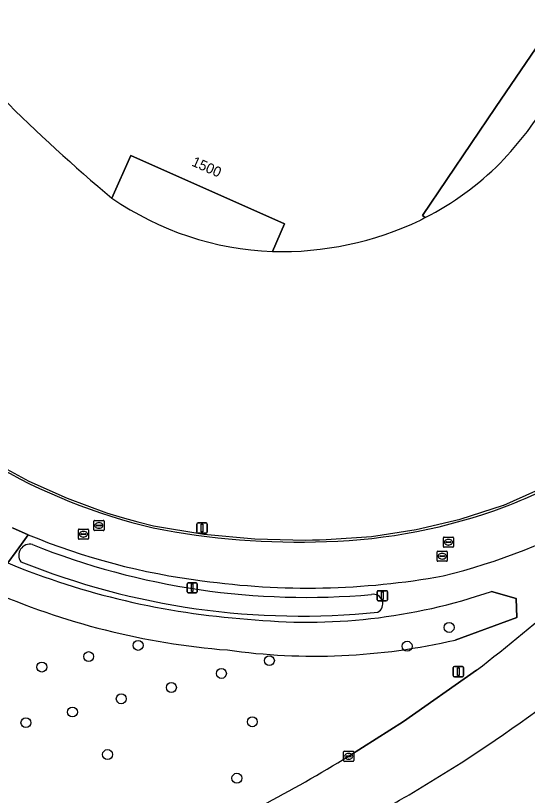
# Model space of a CAD drawing. Extents: x 155018 to 156648, y 383979 to 385733.
# Drawn here: x 155811.6 to 155861.9, y 384237.5 to 384314.2 of the extents above; entities that cross this region are included whole.
import ezdxf

# ---------------------------------------------------------------- set-up
doc = ezdxf.new("R2010")
doc.units = 0
for name, color, linetype in [('IMGEO_Berm_groen', 7, 'Continuous'), ('IMGEO_Boom', 7, 'Continuous'), ('IMGEO_Erf', 7, 'Continuous'), ('IMGEO_Groenvoorziening', 7, 'Continuous'), ('IMGEO_Kolk', 7, 'Continuous'), ('IMGEO_Lichtmast', 7, 'Continuous'), ('IMGEO_Lijnafwatering', 7, 'Continuous'), ('IMGEO_Loofbos', 7, 'Continuous'), ('IMGEO_Pand', 7, 'Continuous'), ('IMGEO_Pand_nummerreeks', 7, 'Continuous'), ('IMGEO_Pand_overbouw', 7, 'Continuous'), ('IMGEO_Rijbaan_lokaal_gesloten', 7, 'Continuous'), ('IMGEO_Rijbaan_regionaal_gesloten', 7, 'Continuous'), ('IMGEO_Rioolput', 7, 'Continuous'), ('IMGEO_Verkeersbordpaal', 7, 'Continuous'), ('IMGEO_Voetpad_halfverhard', 7, 'Continuous'), ('IMGEO_Waterloop', 7, 'Continuous')]:
    doc.layers.add(name, color=color, linetype=linetype)

msp = doc.modelspace()

# ---------------------------------------------------------------- linework, layer by layer
at = {"layer": 'IMGEO_Berm_groen'}
for centre, radius, start, end in [((155773.683, 384367.762), 151.05, 300.47999, 312.64177), ((155821.116, 384295.176), 73.267, 303.48216, 324.29176), ((155768.291, 384380.188), 164.502, 298.36779, 299.90303)]:
    msp.add_arc(centre, radius, start, end, dxfattribs=at)
at = {"layer": 'IMGEO_Boom'}
for centre in [(155854.233, 384254.034), (155823.651, 384252.272), (155850.102, 384252.192), (155818.785, 384251.17), (155836.557, 384250.771), (155814.182, 384250.14), (155831.842, 384249.512), (155826.923, 384248.13), (155821.993, 384247.018), (155817.192, 384245.72), (155812.618, 384244.672), (155834.884, 384244.762), (155820.646, 384241.541), (155833.365, 384239.213)]:
    msp.add_circle(centre, 0.489, dxfattribs=at)
at = {"layer": 'IMGEO_Erf'}
for points in [[(155905.563, 384373.608), (155905.475, 384373.656), (155858.806, 384305.146), (155851.606, 384294.528), (155851.893, 384294.333), (155851.412, 384294.091)], [(155836.857, 384290.997), (155838.061, 384293.72), (155822.941, 384300.446), (155821.077, 384296.245)]]:
    msp.add_lwpolyline(points, dxfattribs=at)
for centre, radius, start, end in [((155924.104, 384419.823), 160.891, 219.75412, 230.18215), ((155837.737, 384322.641), 31.656, 268.4077, 295.5941), ((155835.992, 384326.647), 65.215, 291.29754, 306.77872), ((155838.308, 384319.82), 57.527, 239.57658, 256.76863), ((155840.492, 384317.734), 55.284, 271.73066, 290.30741), ((155839.502, 384337.19), 74.762, 258.92501, 272.03874)]:
    msp.add_arc(centre, radius, start, end, dxfattribs=at)
at = {"layer": 'IMGEO_Groenvoorziening'}
for points in [[(155812.85, 384263.155), (155812.169, 384262.22), (155811.649, 384261.507), (155810.825, 384260.375)], [(155858.391, 384257.572), (155860.825, 384256.893), (155860.893, 384255.009), (155854.833, 384252.797)], [(155860.893, 384255.009), (155860.825, 384256.893), (155858.391, 384257.572)], [(155854.833, 384252.797), (155860.893, 384255.009)], [(155849.757, 384244.793), (155856.932, 384249.833)], [(155844.357, 384241.37), (155849.757, 384244.793)]]:
    msp.add_lwpolyline(points, dxfattribs=at)
for centre, radius, start, end in [((155837.239, 384324.624), 67.545, 284.0594, 298.23768), ((155837.979, 384323.606), 65.466, 247.42756, 262.96403), ((155812.991, 384261.134), 1.081, 75.88665, 215.93561), ((155840.201, 384329.531), 72.539, 248.19351, 275.068), ((155839.603, 384330.316), 75.63, 247.63496, 266.05689), ((155839.603, 384330.316), 75.63, 247.63496, 266.05689), ((155839.711, 384328.998), 73.848, 248.05786, 275.84098), ((155840.345, 384332.577), 74.67, 262.00578, 280.26273), ((155838.133, 384324.163), 72.569, 246.24875, 265.49317), ((155838.133, 384324.163), 72.569, 246.24875, 265.49317), ((155840.286, 384310.367), 55.813, 263.94829, 288.92814), ((155840.286, 384310.367), 55.813, 263.94829, 288.92814), ((155846.777, 384256.355), 0.936, 298.64359, 100.36374), ((155709.195, 384440.561), 241.254, 307.76122, 310.50727), ((155841.011, 384312.342), 61.128, 261.93116, 283.06837), ((155841.011, 384312.342), 61.128, 261.93116, 283.06837), ((155756.649, 384385.642), 168.841, 294.60978, 301.29698)]:
    msp.add_arc(centre, radius, start, end, dxfattribs=at)
at = {"layer": 'IMGEO_Kolk'}
for p, q in [((155843.856, 384240.944), (155843.856, 384241.796)), ((155843.931, 384241.87), (155844.783, 384241.87)), ((155844.344, 384241.65), (155844.369, 384241.65)), ((155844.857, 384241.796), (155844.857, 384240.944)), ((155844.783, 384240.87), (155843.931, 384240.87)), ((155844.115, 384241.364), (155844.115, 384241.376)), ((155844.553, 384241.327), (155844.155, 384241.327)), ((155844.158, 384241.413), (155844.556, 384241.413)), ((155844.367, 384241.09), (155844.342, 384241.09)), ((155844.599, 384241.376), (155844.599, 384241.364))]:
    msp.add_line(p, q, dxfattribs=at)
for points in [[(155843.856, 384240.944), (155843.856, 384241.796)], [(155843.931, 384241.87), (155844.783, 384241.87)], [(155844.857, 384241.796), (155844.857, 384240.944)], [(155844.783, 384240.87), (155843.931, 384240.87)]]:
    msp.add_lwpolyline(points, dxfattribs=at)
for centre, radius, start, end in [((155843.933, 384241.794), 0.0765, 91.55205, 178.44795), ((155843.933, 384241.794), 0.0765, 91.55205, 178.44795), ((155844.781, 384241.794), 0.0765, 1.55205, 88.44795), ((155844.781, 384241.794), 0.0765, 1.55205, 88.44795), ((155843.933, 384240.946), 0.0765, 181.55205, 268.44795), ((155843.933, 384240.946), 0.0765, 181.55205, 268.44795), ((155844.155, 384241.373), 0.0403, 85.87752, 175.75265), ((155844.152, 384241.363), 0.0366, 178.93798, 274.71019), ((155844.556, 384241.37), 0.043, 264.86636, 352.45326), ((155844.56, 384241.375), 0.0386, 1.73085, 96.63898), ((155844.781, 384240.946), 0.0765, 271.55205, 358.44795), ((155844.781, 384240.946), 0.0765, 271.55205, 358.44795)]:
    msp.add_arc(centre, radius, start, end, dxfattribs=at)
for centre, major_axis, ratio, start_param, end_param in [((155844.343, 384241.37), (-0.387, 0.002), 0.722429, 4.712389, 7.853982), ((155844.368, 384241.37), (-0.39, 0.002), 0.717154, 1.570796, 4.712389)]:
    msp.add_ellipse(centre, major_axis=major_axis, ratio=ratio, start_param=start_param, end_param=end_param, dxfattribs=at)
at = {"layer": 'IMGEO_Lichtmast'}
for p, q in [((155847.169, 384256.748), (155847.169, 384257.548)), ((155847.169, 384257.548), (155847.169, 384256.748)), ((155847.269, 384257.648), (155848.059, 384257.648)), ((155848.059, 384257.648), (155847.269, 384257.648)), ((155848.159, 384257.548), (155848.159, 384256.748)), ((155848.159, 384256.748), (155848.159, 384257.548)), ((155848.059, 384256.648), (155847.269, 384256.648)), ((155847.269, 384256.648), (155848.059, 384256.648)), ((155854.647, 384249.295), (155854.647, 384250.095)), ((155854.647, 384250.095), (155854.647, 384249.295)), ((155854.747, 384250.195), (155855.537, 384250.195)), ((155855.537, 384250.195), (155854.747, 384250.195)), ((155855.637, 384250.095), (155855.637, 384249.295)), ((155855.637, 384249.295), (155855.637, 384250.095)), ((155855.537, 384249.195), (155854.747, 384249.195)), ((155854.747, 384249.195), (155855.537, 384249.195))]:
    msp.add_line(p, q, dxfattribs=at)
for points in [[(155847.589, 384257.523), (155847.739, 384257.523), (155847.739, 384256.773), (155847.589, 384256.773), (155847.589, 384257.523)], [(155855.067, 384250.07), (155855.217, 384250.07), (155855.217, 384249.32), (155855.067, 384249.32), (155855.067, 384250.07)]]:
    msp.add_lwpolyline(points, dxfattribs=at)
for centre, start, end in [((155847.269, 384257.548), 90, 180), ((155847.269, 384257.548), 90, 180), ((155848.059, 384257.548), 0, 90), ((155848.059, 384257.548), 360, 90), ((155847.269, 384256.748), 180, 270), ((155847.269, 384256.748), 180, 270), ((155848.059, 384256.748), 270, 0), ((155848.059, 384256.748), 270, 0), ((155854.747, 384250.095), 90, 180), ((155854.747, 384250.095), 90, 180), ((155855.537, 384250.095), 0, 90), ((155855.537, 384250.095), 360, 90), ((155854.747, 384249.295), 180, 270), ((155854.747, 384249.295), 180, 270), ((155855.537, 384249.295), 270, 0), ((155855.537, 384249.295), 270, 0)]:
    msp.add_arc(centre, 0.1, start, end, dxfattribs=at)
at = {"layer": 'IMGEO_Lijnafwatering'}
for points in [[(155859.568, 384266.058), (155859.581, 384266.063), (155859.593, 384266.067), (155859.606, 384266.072), (155864.958, 384268.44), (155870.075, 384271.281), (155874.915, 384274.571), (155875.502, 384275.036), (155876.083, 384275.508), (155876.659, 384275.986)], [(155802.987, 384274.421), (155805.051, 384273.025), (155807.149, 384271.68), (155809.278, 384270.386), (155812.907, 384268.427), (155816.668, 384266.734), (155820.54, 384265.316)], [(155840.121, 384262.63), (155840.799, 384262.639), (155841.477, 384262.654), (155842.155, 384262.675), (155846.597, 384262.989), (155850.999, 384263.661), (155855.332, 384264.686), (155859.568, 384266.058)], [(155820.54, 384265.316), (155822.074, 384264.839), (155823.621, 384264.406), (155825.179, 384264.016), (155830.125, 384263.219), (155835.113, 384262.757), (155840.121, 384262.63)]]:
    msp.add_lwpolyline(points, dxfattribs=at)
at = {"layer": 'IMGEO_Loofbos'}
msp.add_arc((155821.116, 384295.176), 73.267, 303.48216, 324.29176, dxfattribs=at)
at = {"layer": 'IMGEO_Pand'}
for points in [[(155851.412, 384294.091), (155851.893, 384294.333), (155851.606, 384294.528), (155858.806, 384305.146), (155905.475, 384373.656), (155905.563, 384373.608)], [(155821.077, 384296.245), (155822.941, 384300.446), (155838.061, 384293.72), (155836.857, 384290.997)]]:
    msp.add_lwpolyline(points, dxfattribs=at)
for centre, radius, start, end in [((155924.104, 384419.823), 160.891, 219.75412, 230.18215), ((155837.737, 384322.641), 31.656, 268.4077, 295.5941)]:
    msp.add_arc(centre, radius, start, end, dxfattribs=at)
at = {"layer": 'IMGEO_Pand_overbouw'}
for points in [[(155905.563, 384373.608), (155905.475, 384373.656), (155858.806, 384305.146), (155851.606, 384294.528), (155851.893, 384294.333)], [(155836.857, 384290.997), (155838.061, 384293.72), (155822.941, 384300.446), (155821.077, 384296.245)]]:
    msp.add_lwpolyline(points, dxfattribs=at)
for centre, radius, start, end in [((155405.873, 384634.32), 563.823, 323.98586, 327.33472), ((155824.163, 384332.579), 48.097, 316.86776, 321.74754), ((155838.306, 384320.75), 29.707, 297.21792, 314.86733), ((155837.99, 384320.752), 29.777, 235.38953, 267.81902)]:
    msp.add_arc(centre, radius, start, end, dxfattribs=at)
at = {"layer": 'IMGEO_Rijbaan_lokaal_gesloten'}
msp.add_lwpolyline([(155811.293, 384263.827), (155812.85, 384263.155)], dxfattribs=at)
for centre, radius, start, end in [((155835.992, 384326.647), 65.215, 291.29754, 306.77872), ((155838.308, 384319.82), 57.527, 239.57658, 256.76863), ((155840.492, 384317.734), 55.284, 271.73066, 290.30741), ((155837.239, 384324.624), 67.545, 284.0594, 298.23768), ((155839.502, 384337.19), 74.762, 258.92501, 272.03874), ((155837.979, 384323.606), 65.466, 247.42756, 262.96403), ((155840.345, 384332.577), 74.67, 262.00578, 280.26273)]:
    msp.add_arc(centre, radius, start, end, dxfattribs=at)
at = {"layer": 'IMGEO_Rijbaan_regionaal_gesloten'}
msp.add_lwpolyline([(155856.932, 384249.833), (155849.757, 384244.793), (155844.357, 384241.37)], dxfattribs=at)
for centre, radius, start, end in [((155709.195, 384440.561), 241.254, 307.76122, 310.50727), ((155773.683, 384367.762), 151.05, 300.47999, 312.64177), ((155756.649, 384385.642), 168.841, 294.60978, 301.29698), ((155768.291, 384380.188), 164.502, 298.36779, 299.90303)]:
    msp.add_arc(centre, radius, start, end, dxfattribs=at)
at = {"layer": 'IMGEO_Rioolput'}
for p, q in [((155819.295, 384263.634), (155819.295, 384264.486)), ((155819.37, 384264.56), (155820.222, 384264.56)), ((155819.554, 384264.054), (155819.554, 384264.066)), ((155819.992, 384264.017), (155819.594, 384264.017)), ((155819.597, 384264.103), (155819.995, 384264.103)), ((155819.783, 384264.34), (155819.808, 384264.34)), ((155820.038, 384264.066), (155820.038, 384264.054)), ((155820.296, 384264.486), (155820.296, 384263.634)), ((155817.773, 384262.778), (155817.773, 384263.63)), ((155817.848, 384263.704), (155818.7, 384263.704)), ((155818.032, 384263.198), (155818.032, 384263.21)), ((155818.47, 384263.161), (155818.072, 384263.161)), ((155818.075, 384263.247), (155818.473, 384263.247)), ((155818.261, 384263.484), (155818.286, 384263.484)), ((155818.516, 384263.21), (155818.516, 384263.198)), ((155818.774, 384263.63), (155818.774, 384262.778)), ((155820.222, 384263.56), (155819.37, 384263.56)), ((155819.806, 384263.78), (155819.781, 384263.78)), ((155818.7, 384262.704), (155817.848, 384262.704)), ((155818.284, 384262.924), (155818.259, 384262.924)), ((155853.667, 384261.992), (155853.667, 384262.844)), ((155853.742, 384262.918), (155854.594, 384262.918)), ((155853.926, 384262.412), (155853.926, 384262.424)), ((155854.364, 384262.375), (155853.966, 384262.375)), ((155853.969, 384262.461), (155854.367, 384262.461)), ((155854.155, 384262.698), (155854.18, 384262.698)), ((155854.41, 384262.424), (155854.41, 384262.412)), ((155854.668, 384262.844), (155854.668, 384261.992)), ((155853.125, 384261.539), (155853.977, 384261.539)), ((155854.594, 384261.918), (155853.742, 384261.918)), ((155854.178, 384262.138), (155854.153, 384262.138)), ((155853.05, 384260.613), (155853.05, 384261.465)), ((155853.309, 384261.033), (155853.309, 384261.045)), ((155853.747, 384260.996), (155853.349, 384260.996)), ((155853.352, 384261.082), (155853.75, 384261.082)), ((155853.561, 384260.759), (155853.536, 384260.759)), ((155853.538, 384261.319), (155853.563, 384261.319)), ((155853.793, 384261.045), (155853.793, 384261.033)), ((155854.051, 384261.465), (155854.051, 384260.613)), ((155853.977, 384260.539), (155853.125, 384260.539))]:
    msp.add_line(p, q, dxfattribs=at)
for points in [[(155819.295, 384263.634), (155819.295, 384264.486)], [(155819.37, 384264.56), (155820.222, 384264.56)], [(155820.296, 384264.486), (155820.296, 384263.634)], [(155817.773, 384262.778), (155817.773, 384263.63)], [(155817.848, 384263.704), (155818.7, 384263.704)], [(155818.774, 384263.63), (155818.774, 384262.778)], [(155820.222, 384263.56), (155819.37, 384263.56)], [(155818.7, 384262.704), (155817.848, 384262.704)], [(155853.667, 384261.992), (155853.667, 384262.844)], [(155853.742, 384262.918), (155854.594, 384262.918)], [(155854.668, 384262.844), (155854.668, 384261.992)], [(155853.125, 384261.539), (155853.977, 384261.539)], [(155854.594, 384261.918), (155853.742, 384261.918)], [(155853.05, 384260.613), (155853.05, 384261.465)], [(155854.051, 384261.465), (155854.051, 384260.613)], [(155853.977, 384260.539), (155853.125, 384260.539)]]:
    msp.add_lwpolyline(points, dxfattribs=at)
for centre, radius, start, end in [((155819.372, 384264.484), 0.0765, 91.55205, 178.44795), ((155819.372, 384264.484), 0.0765, 91.55205, 178.44795), ((155819.594, 384264.063), 0.0403, 85.87752, 175.75265), ((155819.591, 384264.053), 0.0366, 178.93798, 274.71019), ((155819.995, 384264.06), 0.043, 264.86636, 352.45326), ((155819.999, 384264.065), 0.0386, 1.73085, 96.63898), ((155820.22, 384264.484), 0.0765, 1.55205, 88.44795), ((155820.22, 384264.484), 0.0765, 1.55205, 88.44795), ((155817.85, 384263.628), 0.0765, 91.55205, 178.44795), ((155817.85, 384263.628), 0.0765, 91.55205, 178.44795), ((155818.072, 384263.207), 0.0403, 85.87752, 175.75265), ((155818.069, 384263.197), 0.0366, 178.93798, 274.71019), ((155818.473, 384263.204), 0.043, 264.86636, 352.45326), ((155818.477, 384263.209), 0.0386, 1.73085, 96.63898), ((155818.698, 384263.628), 0.0765, 1.55205, 88.44795), ((155818.698, 384263.628), 0.0765, 1.55205, 88.44795), ((155819.372, 384263.636), 0.0765, 181.55205, 268.44795), ((155819.372, 384263.636), 0.0765, 181.55205, 268.44795), ((155820.22, 384263.636), 0.0765, 271.55205, 358.44795), ((155820.22, 384263.636), 0.0765, 271.55205, 358.44795), ((155817.85, 384262.78), 0.0765, 181.55205, 268.44795), ((155817.85, 384262.78), 0.0765, 181.55205, 268.44795), ((155818.698, 384262.78), 0.0765, 271.55205, 358.44795), ((155818.698, 384262.78), 0.0765, 271.55205, 358.44795), ((155853.744, 384262.842), 0.0765, 91.55205, 178.44795), ((155853.744, 384262.842), 0.0765, 91.55205, 178.44795), ((155853.966, 384262.421), 0.0403, 85.87752, 175.75265), ((155853.963, 384262.411), 0.0366, 178.93798, 274.71019), ((155854.367, 384262.418), 0.043, 264.86636, 352.45326), ((155854.371, 384262.423), 0.0386, 1.73085, 96.63898), ((155854.592, 384262.842), 0.0765, 1.55205, 88.44795), ((155854.592, 384262.842), 0.0765, 1.55205, 88.44795), ((155853.127, 384261.463), 0.0765, 91.55205, 178.44795), ((155853.127, 384261.463), 0.0765, 91.55205, 178.44795), ((155853.744, 384261.994), 0.0765, 181.55205, 268.44795), ((155853.744, 384261.994), 0.0765, 181.55205, 268.44795), ((155853.975, 384261.463), 0.0765, 1.55205, 88.44795), ((155853.975, 384261.463), 0.0765, 1.55205, 88.44795), ((155854.592, 384261.994), 0.0765, 271.55205, 358.44795), ((155854.592, 384261.994), 0.0765, 271.55205, 358.44795), ((155853.349, 384261.042), 0.0403, 85.87752, 175.75265), ((155853.346, 384261.032), 0.0366, 178.93798, 274.71019), ((155853.75, 384261.039), 0.043, 264.86636, 352.45326), ((155853.754, 384261.044), 0.0386, 1.73085, 96.63898), ((155853.127, 384260.615), 0.0765, 181.55205, 268.44795), ((155853.127, 384260.615), 0.0765, 181.55205, 268.44795), ((155853.975, 384260.615), 0.0765, 271.55205, 358.44795), ((155853.975, 384260.615), 0.0765, 271.55205, 358.44795)]:
    msp.add_arc(centre, radius, start, end, dxfattribs=at)
for centre, major_axis, ratio, start_param, end_param in [((155819.782, 384264.06), (-0.387, 0.002), 0.722429, 4.712389, 7.853982), ((155819.807, 384264.06), (-0.39, 0.002), 0.717154, 1.570796, 4.712389), ((155818.26, 384263.204), (-0.387, 0.002), 0.722429, 4.712389, 7.853982), ((155818.285, 384263.204), (-0.39, 0.002), 0.717154, 1.570796, 4.712389), ((155854.154, 384262.418), (-0.387, 0.002), 0.722429, 4.712389, 7.853982), ((155854.179, 384262.418), (-0.39, 0.002), 0.717154, 1.570796, 4.712389), ((155853.537, 384261.039), (-0.387, 0.002), 0.722429, 4.712389, 7.853982), ((155853.562, 384261.039), (-0.39, 0.002), 0.717154, 1.570796, 4.712389)]:
    msp.add_ellipse(centre, major_axis=major_axis, ratio=ratio, start_param=start_param, end_param=end_param, dxfattribs=at)
at = {"layer": 'IMGEO_Verkeersbordpaal'}
for p, q in [((155829.44, 384263.404), (155829.44, 384264.204)), ((155829.44, 384264.204), (155829.44, 384263.404)), ((155829.54, 384264.304), (155830.33, 384264.304)), ((155830.33, 384264.304), (155829.54, 384264.304)), ((155830.43, 384264.204), (155830.43, 384263.404)), ((155830.43, 384263.404), (155830.43, 384264.204)), ((155830.33, 384263.304), (155829.54, 384263.304)), ((155829.54, 384263.304), (155830.33, 384263.304)), ((155828.475, 384257.534), (155828.475, 384258.334)), ((155828.475, 384258.334), (155828.475, 384257.534)), ((155828.575, 384258.434), (155829.365, 384258.434)), ((155829.365, 384258.434), (155828.575, 384258.434)), ((155829.465, 384258.334), (155829.465, 384257.534)), ((155829.465, 384257.534), (155829.465, 384258.334)), ((155829.365, 384257.434), (155828.575, 384257.434)), ((155828.575, 384257.434), (155829.365, 384257.434))]:
    msp.add_line(p, q, dxfattribs=at)
for points in [[(155829.86, 384264.179), (155830.01, 384264.179), (155830.01, 384263.429), (155829.86, 384263.429), (155829.86, 384264.179)], [(155828.895, 384258.309), (155829.045, 384258.309), (155829.045, 384257.559), (155828.895, 384257.559), (155828.895, 384258.309)]]:
    msp.add_lwpolyline(points, dxfattribs=at)
for centre, start, end in [((155829.54, 384264.204), 90, 180), ((155829.54, 384264.204), 90, 180), ((155830.33, 384264.204), 0, 90), ((155830.33, 384264.204), 360, 90), ((155829.54, 384263.404), 180, 270), ((155829.54, 384263.404), 180, 270), ((155830.33, 384263.404), 270, 0), ((155830.33, 384263.404), 270, 0), ((155828.575, 384258.334), 90, 180), ((155828.575, 384258.334), 90, 180), ((155829.365, 384258.334), 0, 90), ((155829.365, 384258.334), 360, 90), ((155828.575, 384257.534), 180, 270), ((155828.575, 384257.534), 180, 270), ((155829.365, 384257.534), 270, 0), ((155829.365, 384257.534), 270, 0)]:
    msp.add_arc(centre, 0.1, start, end, dxfattribs=at)
at = {"layer": 'IMGEO_Voetpad_halfverhard'}
msp.add_lwpolyline([(155810.825, 384260.375), (155811.649, 384261.507), (155812.169, 384262.22), (155812.85, 384263.155), (155811.293, 384263.827)], dxfattribs=at)
at = {"layer": 'IMGEO_Waterloop'}
for centre, radius, start, end in [((155812.991, 384261.134), 1.081, 75.88665, 215.93561), ((155840.201, 384329.531), 72.539, 248.19351, 275.068), ((155839.711, 384328.998), 73.848, 248.05786, 275.84098), ((155846.777, 384256.355), 0.936, 298.64359, 100.36374)]:
    msp.add_arc(centre, radius, start, end, dxfattribs=at)

# ---------------------------------------------------------------- texts
at = {"layer": 'IMGEO_Pand_nummerreeks'}
msp.add_text('1500', height=1, rotation=336.01599, dxfattribs=at).set_placement((155828.837, 384299.465))

doc.saveas('drawing.dxf')
